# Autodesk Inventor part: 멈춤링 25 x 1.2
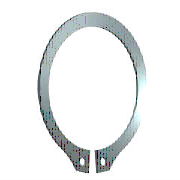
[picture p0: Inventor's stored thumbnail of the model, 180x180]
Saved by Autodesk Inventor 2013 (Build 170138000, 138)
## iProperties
IsCustomPart: 1
Created: 2009-02
Part Number: 멈춤링 25 x 1.2
Material: 강, 연강
Description: 리테이닝 링(C형)
Document SubType Name: Modeling
Standard: KS B 1336
Designer: 진현석
Standards Organization: KS
Language: ko-KR
Size Designation: 25 x 1.2
Categories: <MemberInstance><Categories><Category DisplayName="샤프트 부품" InternalName="7f7aeb1f-a693-4053-b835-cee3144e0d98" Mnemonic="SHFT"><Category DisplayName="써클립" Inter
Density: 1 g/cm^3
Author: 진현석
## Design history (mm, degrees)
sketch "스케치1"
  geometry: L1 (-6, 0)-(6, 0) reference; L2 (0, 20.189)-(0, -80.536) reference; L3 (-48.09, 0)-(48.09, 0) reference; L4 (-0.5, -24.44)-(-0.5, -28.74); L5 (-0.5, -6.54)-(-0.5, -13.29); L6 (-2.795, 3.1)-(3.672, 3.1); L7 (0.5, -6.54)-(0.5, -13.29); L8 (0.5, -24.44)-(0.5, -28.74); C1 r 1 at (-2, -26.606); C2 r 1 at (2, -26.606); A1 r 11.95 centre (0, -12.5) between (0.5, -24.44) and (-0.5, -24.44); A2 r 14.825 centre (0, -11.725) between (5.202, -25.608) and (-5.202, -25.608); A3 r 16.247 centre (0, -12.5) between (-2.281, -28.586) and (-0.5, -28.74); A4 r 2 centre (-2, -26.606) between (-3.952, -27.043) and (-2.281, -28.586); A5 r 2 centre (-5.903, -27.48) between (-3.952, -27.043) and (-5.202, -25.608); A6 r 2 centre (5.903, -27.48) between (5.202, -25.608) and (3.952, -27.043); A7 r 2 centre (2, -26.606) between (2.281, -28.586) and (3.952, -27.043); A8 r 16.247 centre (0, -12.5) between (0.5, -28.74) and (2.281, -28.586)
  constraints: 16 point on circle, 12 end point, 10 centre point, 9 symmetric about line, 5 point on line, 4 tangent, 3 coincident, 2 horizontal, 1 perpendicular, 1 vertical, 5 other
  dimensions: "d0" = 23.9 diameter of A1 (= ND); "d1" = 4.3 distance of L4.end L4.start (= SRB2); "d6" = 0.5 distance between parallel lines of L2 L5 (= 0.25 x SD5); "d7" = 3.1 distance between parallel lines of L6 L3 (= SRB1); "d8" = 0.775 distance of A1.centre A2.centre (= 0.25 x SRB1); "d9" = 2 radius of A4 (= SD5); "d10" = 2 radius of A5 (= SD5); "d11" = 1.5 distance from line of L4 A4.centre (= 0.75 x SD5); "d12" = 2 diameter of C1 (= SD5); "d13" = 2 diameter of C2 (= SD5); "d14" = 12.5 distance from line of A1.centre L1 (= 0.5 x WD)
extrude "본체" new body sketch "스케치1" distance "d2" = 1.2 (= SD); taper "d3" = 0 deg
workaxis "Work Axis1"
workplane "Work Plane1"
body "Solid1"
other parameters: "WD" = 25 (= WDMIN) [user parameter; used in 1 equation term], "SD" = 1.2 [user parameter; used in 1 equation term], "SRB1" = 3.1 [user parameter; used in 2 equation terms], "ND" = 23.9 [user parameter; used in 1 equation term], "SRB2" = 4.3 [user parameter; used in 1 equation term], "SD5" = 2 [user parameter; used in 6 equation terms], "d15" = 0, "d16" = 0, "d17" = 0, "d41" = 0, "d42" = 0, "WDMIN" = 25 [user parameter; used in 1 equation term], "SD3" = 23.2 [user parameter], "WDMAX" = 26 [user parameter]
